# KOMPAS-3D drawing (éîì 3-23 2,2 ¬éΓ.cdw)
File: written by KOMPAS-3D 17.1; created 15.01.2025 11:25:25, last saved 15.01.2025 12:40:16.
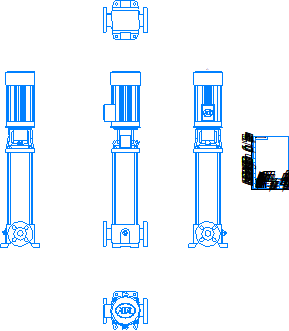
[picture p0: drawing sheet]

Sheet 1: A4, portrait

Title block, sheet 1: name: ВМН 3-23 2,2 кВт; designation: ВМН 3-23 2,2 кВт; material: Сталь 10  ГОСТ 1050-2013; mass: 68,16; sheets: 1; sheet format: A4; stored path: \\adlc.lan\data\АДЛ_ПКД\3D-модели\ADL production\Насосы ГРАНПАМП\Насосы ВМН\ВМН3\KOMPAS 3D\ВМН 3-23 2,2 кВт.cdw

Views: Проекционный вид 2, Проекционный вид 3, Проекционный вид 4, Проекционный вид 5
Referenced files in \\adlc.lan\data\АДЛ_ПКД\3D-модели\ADL production\Насосы ГРАНПАМП\Насосы ВМН\ВМН3\KOMPAS 3D\: ВМН 3-23 2,2 кВт.m3d
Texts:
  Andrey
  АДЛ
Dimensions and other numbers on the sheet: 1:1; 1; 68,16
